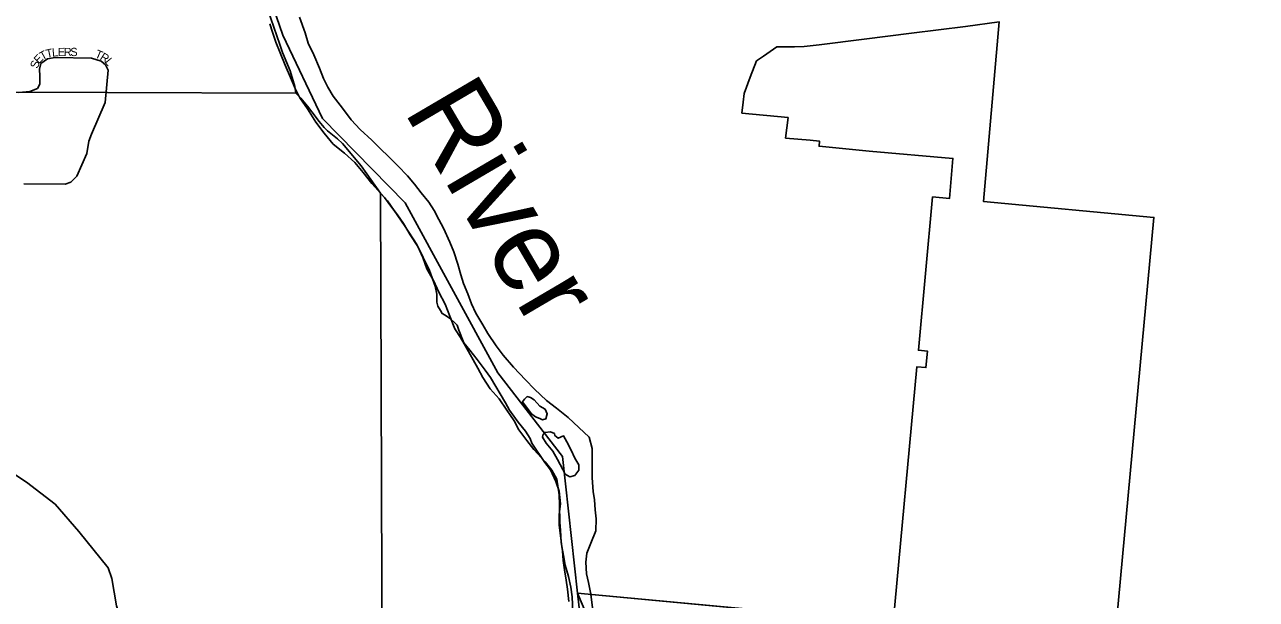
# Model space of a CAD drawing. Extents: x 8.5 to 81.5, y -1.2 to 22.4.
# Drawn here: x 53.822 to 55.233, y 19.28 to 19.938 of the extents above; entities that cross this region are included whole.
import ezdxf

# ---------------------------------------------------------------- set-up
doc = ezdxf.new("R2010")
doc.units = 0
for name, color, linetype in [('GM_X_Adjacent_County', 7, 'Continuous'), ('GM_X_City_Street', 7, 'Continuous'), ('GM_X_City_Street_Text', 7, 'Continuous'), ('GM_X_Corporation', 7, 'Continuous'), ('GM_X_County', 7, 'Continuous'), ('GM_X_Major_River', 7, 'Continuous'), ('GM_X_Major_River_Text', 7, 'Continuous'), ('GM_X_Section', 7, 'Continuous'), ('GM_X_Township', 7, 'Continuous')]:
    doc.layers.add(name, color=color, linetype=linetype)

msp = doc.modelspace()

# ---------------------------------------------------------------- linework, layer by layer
at = {"layer": 'GM_X_Adjacent_County'}
msp.add_lwpolyline([(54.0879, 21.2506), (53.9752, 21.0796), (53.9892, 20.8879), (54.0113, 20.7922), (54.0509, 20.4053), (54.0874, 20.2135), (54.0852, 20.0218), (54.1183, 19.9261), (54.1635, 19.8308), (54.2583, 19.734), (54.3644, 19.5393), (54.4386, 19.4436), (54.4557, 19.2868), (54.6072, 19.2726), (55.071, 19.2296), (55.5754, 19.1818), (55.8177, 19.1557), (56.1419, 19.1206), (56.172, 19.1174), (56.2527, 19.1108)], dxfattribs=at)
at = {"layer": 'GM_X_City_Street'}
for points in [[(53.8157, 19.8606), (53.8281, 19.8618), (53.8369, 19.865), (53.8396, 19.8701), (53.8396, 19.8793), (53.8392, 19.8872), (53.841, 19.8937), (53.8484, 19.8992), (53.8572, 19.9006), (53.8988, 19.9001), (53.9099, 19.8964), (53.9149, 19.8923), (53.9182, 19.8863), (53.9145, 19.8493), (53.8988, 19.8128), (53.896, 19.805), (53.8937, 19.7906), (53.8821, 19.7648), (53.8752, 19.7578), (53.8687, 19.7555), (53.8216, 19.756)], [(53.8157, 18.6929), (53.8318, 18.7013), (53.8454, 18.7192), (53.8528, 18.7471), (53.8764, 18.8483), (53.885, 18.8796), (53.9006, 18.9195), (53.9306, 18.997), (53.9478, 19.0422), (53.9619, 19.1019), (53.9684, 19.1457), (53.9724, 19.1935), (53.9532, 19.2177), (53.9356, 19.25), (53.9274, 19.2725), (53.9223, 19.3037), (53.918, 19.316), (53.8843, 19.3576), (53.8573, 19.3889), (53.8244, 19.4142), (53.7765, 19.4456)]]:
    msp.add_lwpolyline(points, dxfattribs=at)
at = {"layer": 'GM_X_Corporation'}
for points in [[(54.4594, 19.2535), (54.4557, 19.2868), (54.4386, 19.4436), (54.3644, 19.5393), (54.2583, 19.734), (54.1635, 19.8308), (54.1183, 19.9261), (54.0852, 20.0218)], [(55.0709, 19.2291), (55.1161, 19.7174), (54.9209, 19.7355), (54.9389, 19.9415), (54.9002, 19.9364), (54.8382, 19.9286), (54.784, 19.9218), (54.7325, 19.9153), (54.7154, 19.9132), (54.7042, 19.913), (54.6842, 19.9128), (54.6688, 19.9024), (54.6606, 19.8968), (54.6535, 19.8783), (54.6465, 19.8596), (54.6454, 19.8497), (54.644, 19.837), (54.697, 19.8319), (54.6941, 19.8084), (54.7222, 19.806), (54.7329, 19.8049), (54.7325, 19.799), (54.7898, 19.7935), (54.8857, 19.7851), (54.8817, 19.7391), (54.8625, 19.7409), (54.8462, 19.5652), (54.8566, 19.5642), (54.8549, 19.5454), (54.8445, 19.5463), (54.8173, 19.2529), (54.4557, 19.2868), (54.4594, 19.2535)]]:
    msp.add_lwpolyline(points, dxfattribs=at)
at = {"layer": 'GM_X_County'}
msp.add_lwpolyline([(56.2527, 19.1108), (56.172, 19.1174), (56.1419, 19.1206), (55.8177, 19.1557), (55.5754, 19.1818), (55.071, 19.2296), (54.6072, 19.2726), (54.4557, 19.2868), (54.4386, 19.4436), (54.3644, 19.5393), (54.2583, 19.734), (54.1635, 19.8308), (54.1183, 19.9261), (54.0852, 20.0218), (54.0874, 20.2135), (54.0509, 20.4053), (54.0113, 20.7922), (53.9892, 20.8879), (53.9752, 21.0796), (54.0879, 21.2506)], dxfattribs=at)
at = {"layer": 'GM_X_Major_River'}
for points in [[(54.1032, 19.9392), (54.1064, 19.9296), (54.11, 19.9182), (54.1152, 19.906), (54.1206, 19.8918), (54.128, 19.875), (54.1324, 19.8651), (54.1375, 19.8544), (54.1464, 19.8417), (54.1561, 19.8267), (54.1653, 19.8141), (54.1758, 19.8014), (54.1889, 19.7909), (54.2005, 19.7805), (54.2102, 19.7689), (54.2199, 19.7563), (54.2344, 19.7401), (54.2419, 19.7305), (54.2493, 19.7205), (54.2563, 19.7105), (54.2641, 19.6975), (54.2726, 19.6841), (54.2785, 19.6715), (54.2832, 19.6585), (54.2906, 19.6451), (54.2969, 19.6317), (54.3042, 19.6179), (54.3093, 19.6042), (54.3152, 19.5897), (54.3215, 19.5797), (54.3274, 19.5701), (54.3414, 19.5448), (54.3473, 19.5341), (54.3555, 19.5211), (54.3659, 19.5095), (54.3748, 19.4965), (54.383, 19.4842), (54.3885, 19.4739), (54.3975, 19.462), (54.4057, 19.4516), (54.4187, 19.4374), (54.4262, 19.4277), (54.4321, 19.4174), (54.4348, 19.3995), (54.435, 19.3881)], [(54.475, 19.3937), (54.4736, 19.4035), (54.4723, 19.419), (54.4725, 19.4297), (54.4723, 19.4414), (54.4725, 19.4528), (54.4689, 19.4658), (54.4573, 19.4766), (54.4449, 19.4882), (54.4318, 19.499), (54.4202, 19.5075), (54.4064, 19.5207), (54.3963, 19.5314), (54.3824, 19.5457), (54.3705, 19.5596), (54.3627, 19.5703), (54.3531, 19.5845), (54.3472, 19.5945), (54.3394, 19.6079), (54.3342, 19.6186), (54.3299, 19.6297), (54.3251, 19.6419), (54.3222, 19.6518), (54.3186, 19.664), (54.3139, 19.6781), (54.3095, 19.6892), (54.3022, 19.7052), (54.297, 19.7152), (54.2915, 19.7255), (54.2852, 19.7351), (54.2766, 19.7455), (54.2688, 19.7555), (54.261, 19.7651), (54.2498, 19.7767), (54.2397, 19.7867), (54.2296, 19.7963), (54.2199, 19.806), (54.2068, 19.8183), (54.1963, 19.8291), (54.1863, 19.8426), (54.1759, 19.8564), (54.1696, 19.8668), (54.1648, 19.8767), (54.1601, 19.8885), (54.1538, 19.9038), (54.1472, 19.9172), (54.1436, 19.929), (54.1371, 19.947)], [(54.4062, 19.5085), (54.402, 19.5109), (54.3979, 19.5121), (54.3948, 19.5091), (54.3925, 19.5061), (54.398, 19.4988), (54.4029, 19.4923), (54.4074, 19.4891), (54.4127, 19.4872), (54.4157, 19.4856), (54.4195, 19.4867), (54.4211, 19.4923), (54.4185, 19.4977)], [(54.4185, 19.4977), (54.4125, 19.5012), (54.4062, 19.5085)], [(54.4184, 19.4708), (54.4162, 19.4689), (54.4154, 19.4655), (54.4198, 19.4586), (54.4273, 19.4497), (54.4328, 19.4402), (54.4387, 19.4287), (54.4415, 19.4231)], [(54.4295, 19.4699), (54.4249, 19.4718), (54.4184, 19.4708)], [(54.4571, 19.4338), (54.4526, 19.4417), (54.4485, 19.4509), (54.4434, 19.4601), (54.4397, 19.467), (54.4336, 19.4644), (54.4298, 19.4675), (54.4295, 19.4699)], [(54.4415, 19.4231), (54.4469, 19.4202), (54.4526, 19.4216), (54.4573, 19.428), (54.4571, 19.4338)], [(54.435, 19.3881), (54.4355, 19.3684), (54.4361, 19.3585), (54.437, 19.3452), (54.4384, 19.3353), (54.4393, 19.3243), (54.4407, 19.3137), (54.4428, 19.3019), (54.4441, 19.2916), (54.4458, 19.2772)], [(54.4708, 19.2858), (54.4682, 19.2992), (54.4661, 19.3091), (54.4651, 19.3224), (54.4664, 19.3326), (54.4708, 19.3443), (54.4767, 19.3583), (54.4769, 19.3719), (54.4759, 19.3822), (54.475, 19.3937)], [(54.4727, 19.2699), (54.4708, 19.2858)]]:
    msp.add_lwpolyline(points, dxfattribs=at)
at = {"layer": 'GM_X_Section'}
for points in [[(54.1009, 19.9553), (54.1145, 19.9157), (54.1178, 19.9065), (54.1264, 19.8855), (54.1318, 19.8676), (54.1332, 19.86), (53.2697, 19.8629)], [(54.2329, 18.8542), (54.2299, 19.7453), (54.238, 19.7365), (54.2576, 19.7081), (54.2716, 19.6866), (54.2862, 19.6568), (54.2926, 19.6385), (54.2947, 19.6294), (54.2946, 19.6203), (54.2956, 19.6157), (54.2989, 19.6107), (54.3008, 19.6073), (54.3041, 19.6053), (54.3101, 19.6014), (54.315, 19.5968), (54.3179, 19.5941), (54.3197, 19.5884), (54.3255, 19.5739), (54.3322, 19.5654), (54.3407, 19.5547), (54.3499, 19.5424), (54.3562, 19.5339), (54.3731, 19.5048), (54.3778, 19.4964), (54.3878, 19.483), (54.3963, 19.4726), (54.4015, 19.4642), (54.4033, 19.4588), (54.4184, 19.4366), (54.4247, 19.4281), (54.4309, 19.4148), (54.4348, 19.4037), (54.4361, 19.3893), (54.4347, 19.3772), (54.4348, 19.3647), (54.4378, 19.3404), (54.4395, 19.3301), (54.4416, 19.3191), (54.4455, 19.3058), (54.4479, 19.2936), (54.4496, 19.2826), (54.4504, 19.2652)]]:
    msp.add_lwpolyline(points, dxfattribs=at)
msp.add_lwpolyline([(53.2345, 19.8635), (53.2697, 19.8629), (54.1332, 19.86), (54.1387, 19.8542), (54.1465, 19.845), (54.1513, 19.8385), (54.1598, 19.8273), (54.1654, 19.8204), (54.1691, 19.8165), (54.1807, 19.8076), (54.1866, 19.8022), (54.2077, 19.7764), (54.2144, 19.7672), (54.2299, 19.7453), (54.2329, 18.8542), (53.2294, 18.8627)], close=True, dxfattribs=at)
at = {"layer": 'GM_X_Township'}
msp.add_lwpolyline([(54.4654, 19.2642), (54.4557, 19.2868), (54.4386, 19.4436), (54.3644, 19.5393), (54.2583, 19.734), (54.1635, 19.8308), (54.1183, 19.9261), (54.0852, 20.0218)], dxfattribs=at)

# ---------------------------------------------------------------- texts
at = {"layer": 'GM_X_City_Street_Text'}
for s, rotation, p in [('T', 12.3658, (53.8478, 19.9002)), ('L', 4.868, (53.854, 19.9016)), ('E', 0.8469, (53.8604, 19.9022)), ('R', 0, (53.8671, 19.9023)), ('S', 0, (53.8746, 19.9023)), ('S', 71.254, (53.8372, 19.8874)), ('E', 47.7447, (53.8388, 19.8928)), ('T', 29.0705, (53.8426, 19.8973)), ('T', 336.8947, (53.9021, 19.9013)), ('R', 327.92, (53.9078, 19.8989)), ('L', 309.1164, (53.9136, 19.8955))]:
    msp.add_text(s, height=0.00947, rotation=rotation, dxfattribs=at).set_placement(p)
at = {"layer": 'GM_X_Major_River_Text'}
msp.add_text('River', height=0.09467, rotation=300.4313, dxfattribs=at).set_placement((54.2558, 19.8399))

doc.saveas('drawing.dxf')
